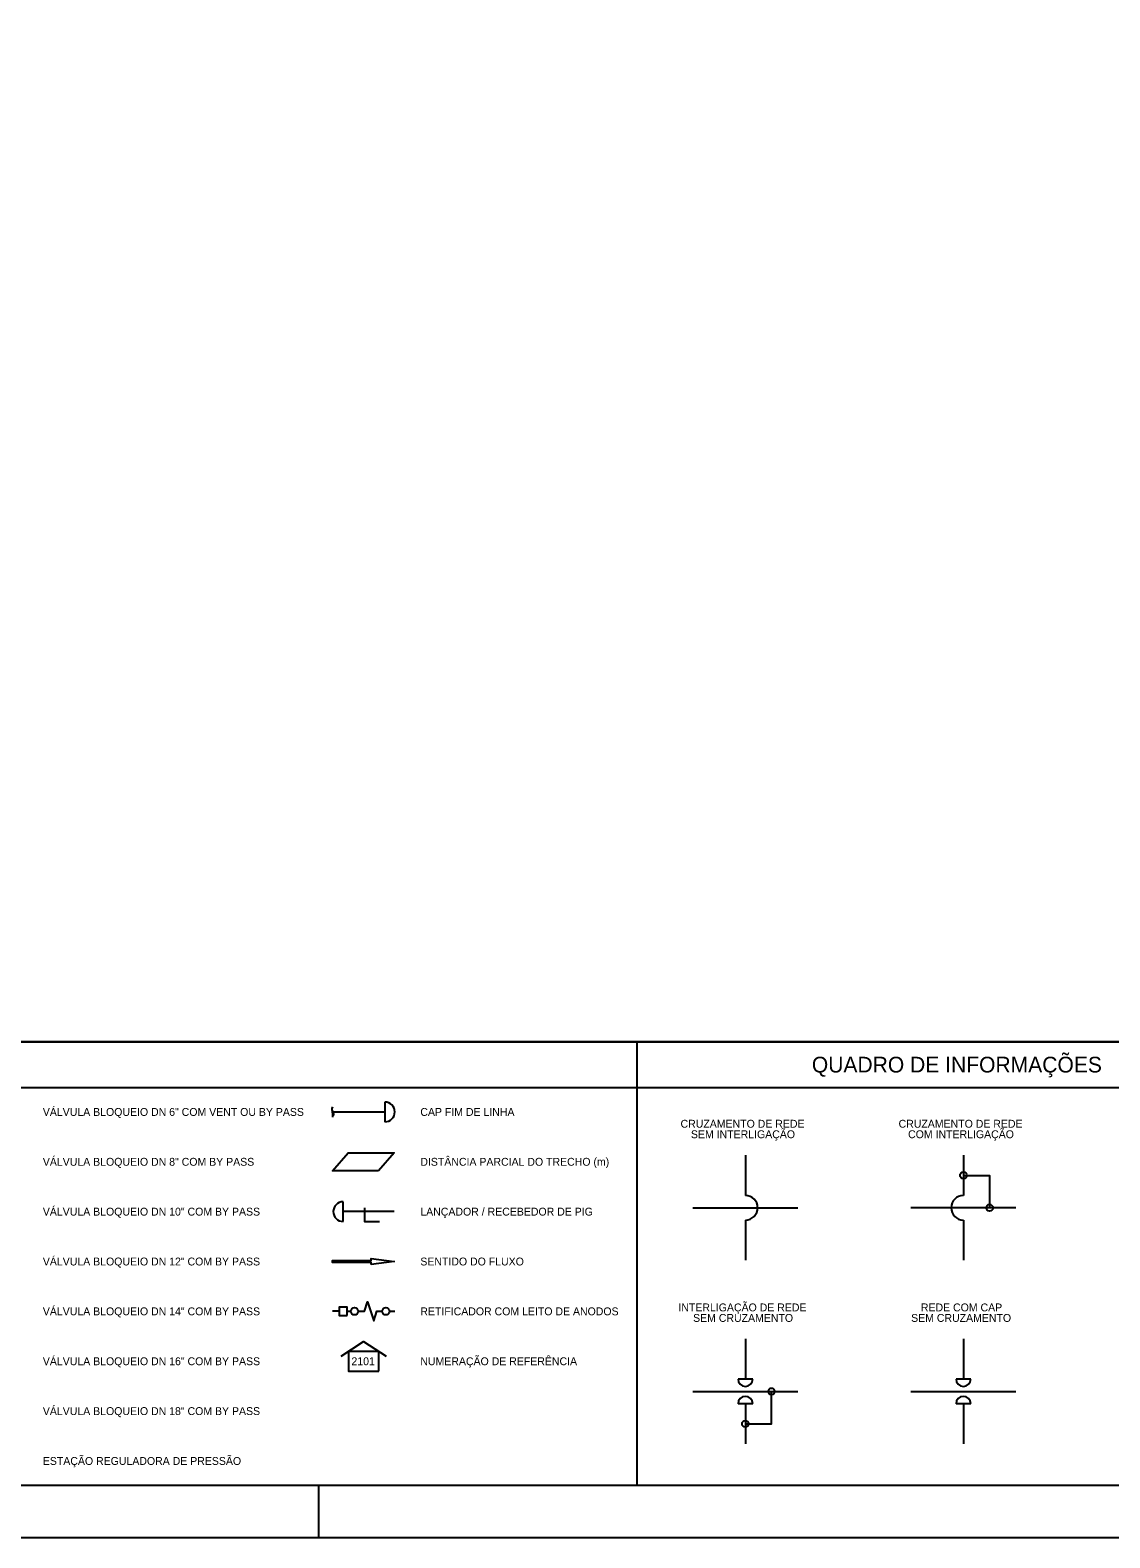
# Model space of a CAD drawing. Extents: x 0 to 841, y 0 to 594.
# Drawn here: x 416 to 621.7, y 0 to 287.3 of the extents above; entities that cross this region are included whole.
import ezdxf

# ---------------------------------------------------------------- set-up
doc = ezdxf.new("R2010")
doc.units = 0
for name, color, linetype in [('FORMATO', 7, 'Continuous'), ('LEGENDA', 7, 'Continuous'), ('MEIO_FIO_GUIA', 7, 'Continuous')]:
    doc.layers.add(name, color=color, linetype=linetype)

msp = doc.modelspace()

# ---------------------------------------------------------------- linework, layer by layer
at = {"layer": 'FORMATO'}
for p, q in [((831.01, 94.54), (25, 94.54)), ((531.63, 10), (531.63, 94.54)), ((25, 85.81), (656, 85.81)), ((831.01, 10), (5, 10)), ((471, 0), (471, 10))]:
    msp.add_line(p, q, dxfattribs=at)
msp.add_lwpolyline([(0, 594), (841, 594), (841, 0), (0, 0)], close=True, dxfattribs=at)
at = {"layer": 'LEGENDA'}
for p, q in [((473.6, 81.16), (483.59, 81.16)), ((483.59, 83.04), (483.59, 79.29)), ((552.27, 72.91), (552.27, 65.25)), ((593.82, 72.91), (593.82, 65.25)), ((475.62, 60.28), (475.62, 64.03)), ((485.33, 62.16), (475.62, 62.16)), ((542.27, 62.91), (562.27, 62.91)), ((552.27, 60.56), (552.27, 52.91)), ((603.82, 62.91), (583.82, 62.91)), ((593.82, 60.56), (593.82, 52.91)), ((474.84, 43.17), (473.6, 43.17)), ((476.38, 43.17), (477.08, 43.17)), ((484.47, 43.18), (485.46, 43.18)), ((552.27, 37.91), (552.27, 30.25)), ((593.82, 37.91), (593.82, 30.25)), ((553.67, 30.25), (550.87, 30.25)), ((595.22, 30.25), (592.42, 30.25)), ((542.27, 27.91), (562.27, 27.91)), ((583.82, 27.91), (603.82, 27.91)), ((553.67, 25.56), (550.87, 25.56)), ((552.27, 25.56), (552.27, 17.91)), ((595.22, 25.56), (592.42, 25.56)), ((593.82, 25.56), (593.82, 17.91))]:
    msp.add_line(p, q, dxfattribs=at)
for points in [[(482.33, 69.97), (473.6, 69.97), (476.6, 73.35), (485.33, 73.35)], [(480.93, 52.09), (480.93, 52.47), (473.6, 52.47), (473.6, 52.84), (480.93, 52.84), (480.93, 53.22), (485.33, 52.66)], [(480.93, 52.09), (480.93, 52.47), (473.6, 52.47), (473.6, 52.84), (480.93, 52.84), (480.93, 53.22), (485.33, 52.66)], [(482.41, 31.78), (482.41, 35.53), (476.66, 35.53), (476.66, 31.78)]]:
    msp.add_lwpolyline(points, close=True, dxfattribs=at)
for points in [[(593.82, 69.08), (598.82, 69.08), (598.82, 62.91)], [(479.7, 62.88), (479.7, 60.28), (482.57, 60.28)], [(476.38, 42.4), (476.38, 43.94), (474.84, 43.94), (474.84, 42.4), (476.38, 42.4)], [(478.48, 43.18), (479.66, 43.18), (480.26, 44.98), (481.47, 41.38), (482.07, 43.18), (483.07, 43.18)], [(475.22, 34.59), (479.53, 37.4), (483.85, 34.59)], [(552.27, 21.73), (557.27, 21.73), (557.27, 27.91)]]:
    msp.add_lwpolyline(points, dxfattribs=at)
for centre, radius in [((593.82, 69.08), 0.633), ((598.82, 62.91), 0.633), ((477.78, 43.17), 0.701), ((483.77, 43.17), 0.701), ((557.27, 27.91), 0.633), ((552.27, 21.73), 0.633)]:
    msp.add_circle(centre, radius, dxfattribs=at)
for centre, radius, start, end in [((483.59, 81.16), 1.88, 270, 90), ((475.62, 62.16), 1.88, 90, 270), ((552.27, 62.91), 2.34, 270, 90), ((593.82, 62.91), 2.34, 90, 270), ((552.27, 30.25), 1.4, 180, 0), ((593.82, 30.25), 1.4, 180, 0), ((552.27, 25.56), 1.4, 0, 180), ((593.82, 25.56), 1.4, 0, 180)]:
    msp.add_arc(centre, radius, start, end, dxfattribs=at)
msp.add_open_spline([(473.6, 82.16), (473.35, 81.66), (473.6, 81.16), (473.85, 80.66), (473.6, 80.16), (473.6, 82.16), (473.6, 80.16)], degree=3, dxfattribs=at)
at = {"layer": 'MEIO_FIO_GUIA'}
msp.add_lwpolyline([(25, 584), (25, 94.54), (572.92, 94.54), (831.01, 94.54), (831.01, 251.27), (831.01, 584)], close=True, dxfattribs=at)

# ---------------------------------------------------------------- texts
at = {"layer": 'FORMATO'}
msp.add_text('QUADRO DE INFORMAÇÕES', height=3, rotation=360, dxfattribs=at).set_placement((564.94, 88.68))
at = {"layer": 'LEGENDA'}
for s, p in [('VÁLVULA BLOQUEIO DN 6" COM VENT OU BY PASS', (418.39, 80.41)), ('CAP FIM DE LINHA', (490.33, 80.41)), ('CRUZAMENTO DE REDE', (539.92, 78.16)), ('SEM INTERLIGAÇÃO', (541.9, 76.16)), ('CRUZAMENTO DE REDE', (581.47, 78.16)), ('COM INTERLIGAÇÃO', (583.28, 76.16)), ('VÁLVULA BLOQUEIO DN 8" COM BY PASS', (418.39, 70.91)), ('DISTÂNCIA PARCIAL DO TRECHO (m)', (490.33, 70.91)), ('VÁLVULA BLOQUEIO DN 10" COM BY PASS', (418.39, 61.41)), ('LANÇADOR / RECEBEDOR DE PIG', (490.33, 61.41)), ('VÁLVULA BLOQUEIO DN 12" COM BY PASS', (418.39, 51.91)), ('SENTIDO DO FLUXO', (490.33, 51.91)), ('VÁLVULA BLOQUEIO DN 14" COM BY PASS', (418.39, 42.41)), ('RETIFICADOR COM LEITO DE ANODOS', (490.33, 42.41)), ('INTERLIGAÇÃO DE REDE', (539.51, 43.16)), ('REDE COM CAP', (585.72, 43.16)), ('SEM CRUZAMENTO', (542.31, 41.16)), ('SEM CRUZAMENTO', (583.86, 41.16)), ('VÁLVULA BLOQUEIO DN 16" COM BY PASS', (418.39, 32.9)), ('NUMERAÇÃO DE REFERÊNCIA', (490.33, 32.9)), ('2101', (477.2, 32.9)), ('VÁLVULA BLOQUEIO DN 18" COM BY PASS', (418.39, 23.4)), ('ESTAÇÃO REGULADORA DE PRESSÃO', (418.39, 13.9))]:
    msp.add_text(s, height=1.5, dxfattribs=at).set_placement(p)

doc.saveas('drawing.dxf')
